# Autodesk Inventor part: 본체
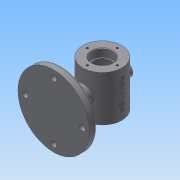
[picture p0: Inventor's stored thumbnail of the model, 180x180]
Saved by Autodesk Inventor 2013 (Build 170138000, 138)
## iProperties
Created: 2018-12
Part Number: 본체
Material: 일반
Document SubType Name: Modeling
Designer: Administrator
Density: 1 g/cm^3
Author: Administrator
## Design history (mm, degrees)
sketch "스케치1"
  geometry: C1 r 30 at (0, 0); 1 further point
  constraints: 1 centre point, 1 coincident
  dimensions: "d0" = 60 diameter of C1
extrude "돌출1" new body sketch "스케치1" distance "d1" = 35; taper "d2" = 0 deg
hole "구멍1" diameter "d5" = 50; stored, may be unused: countersink angle "d9" = 90 deg, drill point angle "d11" = 0 deg; dims "d3" = 10, "d4" = 10, "d6" = 6, "d7" = 4, "d8" = 2, "d10" = 20
hole "구멍2" diameter "d14" = 28; stored, may be unused: countersink angle "d18" = 90 deg, drill point angle "d20" = 0 deg; dims "d12" = 10, "d13" = 10, "d15" = 6, "d16" = 32, "d17" = 12, "d19" = 20
sketch "스케치2"
  geometry: 2 further points
  constraints: 1 vertical alignment
  dimensions: "d21" = 23 distance of point (0, 23) point (0, 0)
hole "구멍3" sketch "스케치2" at (0, 23) diameter "d22" = 3.242; stored, may be unused: countersink angle "d26" = 90 deg, drill point angle "d28" = 118 deg; dims "d23" = 8, "d24" = 32, "d25" = 12, "d27" = 10
chamfer "모따기1" distance "d32" = 1; stored, may be unused: second distance "d33" = 2, angle "d34" = 45 deg
fillet "모깎기1" dims "d35" = 0.3
fillet "모깎기2" dims "d36" = 3
node "작업 평면1"
sketch "스케치3"
  geometry: C1 r 55 at (0, 0); 1 further point
  constraints: 1 centre point, 1 coincident
  dimensions: "d38" = 110 diameter of C1
extrude "돌출2" join sketch "스케치3" distance "d39" = 11; taper "d40" = 0 deg
sketch "스케치4"
  geometry: C1 r 12 at (0, 0); 1 further point
  constraints: 1 centre point, 1 coincident
  dimensions: "d41" = 24 diameter of C1
extrude "돌출3" join sketch "스케치4" stored distance "d42" = 10; taper "d43" = 0 deg
sketch "스케치6"
  geometry: C1 r 55 at (0, 0) reference; 1 further point
extrude "돌출4" join sketch "스케치6" distance "d44" = 13; taper "d45" = -75 deg
sketch "스케치7"
  geometry: 2 further points
  constraints: 1 vertical alignment
  dimensions: "d46" = 44 distance of point (0, 44) point (0, 0)
hole "구멍4" sketch "스케치7" at (0, 44) diameter "d47" = 9; stored, may be unused: countersink angle "d51" = 90 deg, drill point angle "d53" = 0 deg; dims "d48" = 8, "d49" = 32, "d50" = 12, "d52" = 10
hole "구멍6" diameter "d65" = 14; stored, may be unused: countersink angle "d69" = 90 deg, drill point angle "d71" = 0 deg; dims "d63" = 10, "d64" = 10, "d66" = 8, "d67" = 32, "d68" = 12, "d70" = 30
node "작업 평면2"
sketch "스케치8"
  geometry: C1 r 10 at (0, 0); 1 further point
  constraints: 1 centre point, 1 coincident
  dimensions: "d76" = 20 diameter of C1
extrude "돌출5" join sketch "스케치8" stored distance "d77" = 13; taper "d78" = 0 deg
hole "구멍7" diameter "d81" = 10; stored, may be unused: countersink angle "d85" = 90 deg, drill point angle "d87" = 0 deg; dims "d79" = 10, "d80" = 10, "d82" = 8, "d83" = 32, "d84" = 12, "d86" = 30
fillet "모깎기3" dims "d88" = 3
node "작업 평면3"
sketch "스케치9"
  geometry: L1 (30, 35)-(-30, 35) reference; L2 (30, -35)-(30, 35) reference; 2 further points
  constraints: 1 other
  dimensions: "d90" = 35 distance from line of point (0, 0) L1; "d91" = 30 distance from line of point (0, 0) L2
feature "엠보싱1" sketch "스케치9" dims "d32" = 1, "d92" = 0.5, "d93" = 0
chamfer "모따기2" distance "d94" = 1; stored, may be unused: second distance "d95" = 2, angle "d96" = 45 deg
node "솔리드1"
pattern_circular "원형 패턴1" dims angle "d30" = 360 deg
mirror "대칭1"
pattern_circular "원형 패턴2" dims angle "d73" = 360 deg
other parameters: "d37" = -75, "d75" = -112, "d89" = 104
